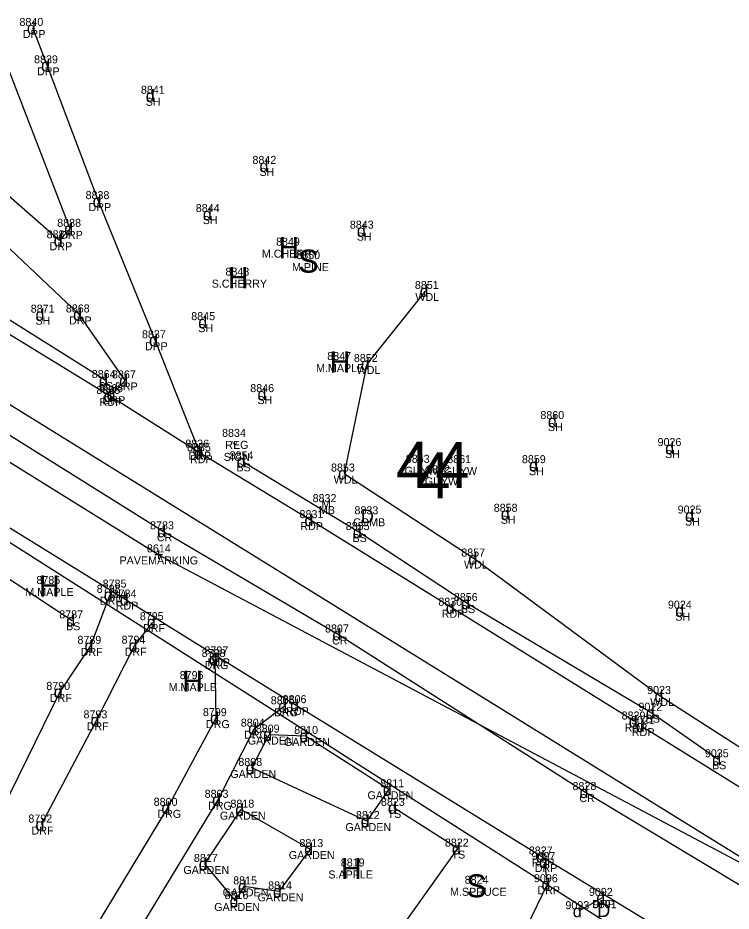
# Model space of a CAD drawing. Extents: x 69415 to 80913, y 7576 to 15059.
# Drawn here: x 77884.6 to 78062.8, y 12956.1 to 13179.4 of the extents above; entities that cross this region are included whole.
import ezdxf

# ---------------------------------------------------------------- set-up
doc = ezdxf.new("R2010")
doc.units = 0
for name, color, linetype in [('Level 11', 7, 'Continuous'), ('Level 12', 7, 'Continuous'), ('Level 14', 7, 'Continuous'), ('Level 15', 7, 'Continuous'), ('Level 43', 7, 'Continuous'), ('Level 45', 7, 'Continuous'), ('Level 46', 7, 'Continuous'), ('Level 47', 7, 'Continuous'), ('Level 48', 7, 'Continuous')]:
    doc.layers.add(name, color=color, linetype=linetype)

msp = doc.modelspace()

# ---------------------------------------------------------------- linework, layer by layer
at = {"layer": 'Level 11'}
for p, q in [((77897.68, 13126.63), (77877.49, 13178.8)), ((77891.9, 13167.5), (77888.34, 13176.83)), ((77904.77, 13133.56), (77891.9, 13167.5)), ((77870.35, 13145.35), (77895.03, 13123.77)), ((77899.89, 13105.23), (77866.57, 13136.78)), ((77918.86, 13098.79), (77904.77, 13133.56)), ((77895.03, 13123.77), (77897.68, 13126.63)), ((77907.51, 13084.89), (77855.14, 13117.01)), ((77911.41, 13088.74), (77899.89, 13105.23)), ((77929.73, 13071.45), (77918.86, 13098.79)), ((77908.27, 13085.31), (77911.41, 13088.74)), ((77930.11, 13070.56), (77907.51, 13084.89)), ((77957.66, 13053.83), (77930.11, 13070.56)), ((77871.92, 13058.45), (77911.53, 13033.98)), ((77992.99, 13031.93), (77957.66, 13053.83)), ((77907.55, 13035.17), (77902.75, 13022.41)), ((77911.53, 13033.98), (77934.46, 13019.78)), ((78038.7, 13003.51), (77992.99, 13031.93)), ((77913.75, 13022.44), (77918.32, 13028.34)), ((77902.75, 13022.41), (77895.05, 13010.92)), ((77904.25, 13003.8), (77913.75, 13022.44)), ((77933.78, 13019.11), (77934.09, 13004.36)), ((77934.46, 13019.78), (77954.13, 13007.59)), ((77895.05, 13010.92), (77880.63, 12981.5)), ((77943.63, 13001.72), (77951.11, 13007.31)), ((77954.13, 13007.59), (78015.5, 12969.77)), ((77890.47, 12977.76), (77904.25, 13003.8)), ((77934.09, 13004.36), (77921.94, 12981.94)), ((77934.6, 12983.95), (77943.63, 13001.72)), ((78040.51, 13002.35), (78086.37, 12973.81)), ((77912.5, 12947.44), (77934.6, 12983.95)), ((77921.94, 12981.94), (77904.19, 12952.44)), ((78015.5, 12969.77), (78057.41, 12944.28)), ((78016.92, 12962.84), (78016.25, 12968.4)), ((78011.78, 12952.23), (78016.92, 12962.84)), ((78030.6, 12959.43), (78024.73, 12956.11))]:
    msp.add_line(p, q, dxfattribs=at)
at = {"layer": 'Level 12'}
for p, q in [((77943.01, 12991.91), (77947.37, 13000.24)), ((77947.37, 13000.24), (77956.41, 12999.9)), ((77956.41, 12999.9), (77977.27, 12986.58)), ((77971.74, 12978.62), (77943.01, 12991.91)), ((77977.27, 12986.58), (77971.74, 12978.62)), ((77931.27, 12967.91), (77940.39, 12981.48)), ((77940.39, 12981.48), (77957.62, 12971.64)), ((77957.62, 12971.64), (77949.81, 12961.07)), ((77938.98, 12958.66), (77931.27, 12967.91)), ((77941.08, 12962.3), (77938.98, 12958.66)), ((77949.81, 12961.07), (77941.08, 12962.3))]:
    msp.add_line(p, q, dxfattribs=at)
at = {"layer": 'Level 14'}
for p, q in [((77986.47, 13111.1), (77971.79, 13092.85)), ((77971.79, 13092.85), (77966.08, 13065.48)), ((77966.08, 13065.48), (77998.63, 13044.24)), ((77998.63, 13044.24), (78045.15, 13009.88)), ((78045.15, 13009.88), (78073.47, 12991.56))]:
    msp.add_line(p, q, dxfattribs=at)
at = {"layer": 'Level 15'}
msp.add_line((77872.12, 13054.89), (78265.18, 12804.76), dxfattribs=at)
at = {"layer": 'Level 45'}
for p, q in [((77735.64, 13173.7), (78075.52, 12963.26)), ((77919.58, 13045.27), (77729.52, 13163.12)), ((78078.46, 12961.08), (77919.58, 13045.27))]:
    msp.add_line(p, q, dxfattribs=at)
at = {"layer": 'Level 48'}
for p, q in [((77906.36, 13088.84), (77856.67, 13120.07)), ((77881.52, 13075.74), (77920.88, 13051.04)), ((77940.76, 13068.52), (77969.77, 13050.87)), ((77862.42, 13052.33), (77898.19, 13028.79)), ((77920.88, 13051.04), (77964.67, 13025.26)), ((77969.77, 13050.87), (77996.83, 13033.11)), ((77996.83, 13033.11), (78042.97, 13005.71)), ((77964.67, 13025.26), (78026.42, 12985.87)), ((78042.97, 13005.71), (78059.56, 12994.07)), ((78026.42, 12985.87), (78074.53, 12956.86)), ((77994.53, 12971.75), (77978.56, 12981.92)), ((77975.6, 12945.31), (77994.53, 12971.75))]:
    msp.add_line(p, q, dxfattribs=at)

# ---------------------------------------------------------------- texts
at = {"layer": 'Level 12'}
msp.add_text('M', height=2.2, dxfattribs=at).set_placement((77960.39, 13056.73))
at = {"layer": 'Level 14'}
for s, height, p in [('H', 5.3, (77949.72, 13119.28)), ('S', 5.75, (77954.61, 13115.69)), ('H', 5.3, (77937.06, 13111.79)), ('H', 5.3, (77962.5, 13090.69)), ('H', 5.3, (77889.88, 13034.73)), ('H', 5.3, (77925.68, 13010.95)), ('H', 5.3, (77965.32, 12964.13)), ('S', 5.75, (77996.6, 12959.58))]:
    msp.add_text(s, height=height, dxfattribs=at).set_placement(p)
at = {"layer": 'Level 15'}
for s, height, p in [('4', 11.5, (77979.06, 13061.91)), ('4', 11.5, (77988.86, 13061.84)), ('4', 11.5, (77984.14, 13059.28)), ('D', 3.4, (77970.25, 13053.1)), ('I', 1.7, (77908.18, 13035.63)), ('D', 3.4, (78029.32, 12954.66))]:
    msp.add_text(s, height=height, dxfattribs=at).set_placement(p)
at = {"layer": 'Level 43'}
msp.add_text('Y', height=1.7, dxfattribs=at).set_placement((77938.02, 13071.79))
at = {"layer": 'Level 46'}
for s, p in [('8840', (77884.99, 13177.33)), ('DRP', (77885.83, 13174.33)), ('8839', (77888.64, 13168)), ('DRP', (77889.39, 13165)), ('8841', (77915.33, 13160.38)), ('SH', (77916.52, 13157.38)), ('8842', (77943.2, 13142.86)), ('SH', (77944.95, 13139.86)), ('8838', (77901.51, 13134.06)), ('DRP', (77902.26, 13131.06)), ('8844', (77929.04, 13130.82)), ('8888', (77894.42, 13127.13)), ('SH', (77930.79, 13127.82)), ('8843', (77967.53, 13126.68)), ('8887', (77891.77, 13124.27)), ('DRP', (77895.17, 13124.13)), ('8849', (77949.1, 13122.43)), ('SH', (77969.27, 13123.68)), ('DRP', (77892.52, 13121.27)), ('M.CHERRY', (77945.55, 13119.43)), ('8850', (77954.14, 13119.06)), ('M.PINE', (77953.09, 13116.06)), ('8848', (77936.45, 13114.94)), ('S.CHERRY', (77933.02, 13111.94)), ('8851', (77983.78, 13111.6)), ('WDL', (77983.89, 13108.6)), ('8871', (77887.8, 13105.68)), ('8868', (77896.58, 13105.73)), ('SH', (77888.99, 13102.68)), ('DRP', (77897.38, 13102.73)), ('8845', (77927.91, 13103.81)), ('SH', (77929.66, 13100.81)), ('8837', (77915.6, 13099.29)), ('DRP', (77916.35, 13096.29)), ('8847', (77961.89, 13093.84)), ('8852', (77968.53, 13093.35)), ('M.MAPLE', (77959.09, 13090.84)), ('8864', (77903.05, 13089.34)), ('8867', (77908.1, 13089.24)), ('WDL', (77969.21, 13090.35)), ('BS', (77904.8, 13086.34)), ('DRP', (77908.89, 13086.24)), ('8865', (77904.21, 13085.39)), ('8866', (77904.91, 13085.81)), ('8846', (77942.65, 13085.83)), ('RDP', (77905, 13082.39)), ('DRP', (77905.76, 13082.81)), ('SH', (77944.45, 13082.83)), ('8860', (78015.13, 13079.09)), ('SH', (78017.01, 13076.09)), ('8834', (77935.61, 13074.64)), ('8836', (77926.42, 13071.95)), ('8835', (77926.85, 13071.06)), ('REG', (77936.4, 13071.64)), ('9026', (78044.41, 13072.35)), ('DRP', (77927.22, 13068.95)), ('SIGN', (77936.02, 13068.64)), ('8854', (77937.5, 13069.02)), ('SH', (78046.3, 13069.35)), ('RDP', (77927.6, 13068.06)), ('8863', (77981.51, 13068.16)), ('8861', (77991.87, 13068.09)), ('8859', (78010.52, 13068.07)), ('BS', (77939.2, 13066.02)), ('8853', (77962.82, 13065.98)), ('GUYW', (77981.21, 13065.16)), ('8862', (77986.58, 13065.53)), ('GUYW', (77991, 13065.09)), ('SH', (78012.28, 13065.07)), ('WDL', (77963.49, 13062.98)), ('GUYW', (77986.28, 13062.53)), ('8832', (77958.23, 13058.33)), ('MB', (77959.8, 13055.33)), ('8833', (77968.69, 13055.3)), ('8858', (78003.48, 13055.92)), ('9025', (78049.43, 13055.48)), ('8831', (77954.97, 13054.33)), ('SH', (78005.23, 13052.92)), ('8783', (77917.62, 13051.54)), ('RDP', (77955.15, 13051.33)), ('8855', (77966.51, 13051.37)), ('COMB', (77968.34, 13052.3)), ('SH', (78051.26, 13052.48)), ('CR', (77919.32, 13048.54)), ('BS', (77968.21, 13048.37)), ('8614', (77916.84, 13045.77)), ('8857', (77995.37, 13044.74)), ('PAVEMARKING', (77909.99, 13042.77)), ('WDL', (77996.04, 13041.74)), ('8786', (77889.22, 13037.88)), ('M.MAPLE', (77886.47, 13034.88)), ('8788', (77904.29, 13035.67)), ('8785', (77905.77, 13036.98)), ('DRF', (77905.09, 13032.67)), ('MH', (77907.4, 13033.98)), ('8784', (77908.27, 13034.48)), ('8856', (77993.51, 13033.61)), ('RDP', (77909.02, 13031.48)), ('8830', (77989.64, 13032.43)), ('BS', (77995.27, 13030.61)), ('9024', (78047, 13031.72)), ('8787', (77894.93, 13029.29)), ('8795', (77915.06, 13028.84)), ('RDP', (77990.47, 13029.43)), ('SH', (78048.83, 13028.72)), ('BS', (77896.63, 13026.29)), ('DRF', (77915.85, 13025.84)), ('8807', (77961.33, 13025.76)), ('8789', (77899.48, 13022.91)), ('8794', (77910.49, 13022.94)), ('CR', (77963.1, 13022.76)), ('DRF', (77900.28, 13019.91)), ('DRF', (77911.28, 13019.94)), ('8798', (77930.52, 13019.61)), ('8797', (77931.2, 13020.28)), ('RDP', (77931.95, 13017.28)), ('DRG', (77931.27, 13016.61)), ('8796', (77925.02, 13014.1)), ('8790', (77891.7, 13011.42)), ('M.MAPLE', (77922.27, 13011.1)), ('9023', (78041.81, 13010.38)), ('DRF', (77892.58, 13008.42)), ('8806', (77950.74, 13008.09)), ('8805', (77947.77, 13007.81)), ('9022', (78039.63, 13006.21)), ('WDL', (78042.57, 13007.38)), ('8793', (77900.99, 13004.3)), ('8799', (77930.82, 13004.86)), ('DRG', (77948.6, 13004.81)), ('RDP', (77951.62, 13005.09)), ('8829', (78035.43, 13004.01)), ('DRG', (77931.58, 13001.86)), ('8804', (77940.29, 13002.22)), ('9021', (78037.74, 13002.85)), ('BS', (78041.41, 13003.21)), ('DRF', (77901.78, 13001.3)), ('DRG', (77941.11, 12999.22)), ('8809', (77944.02, 13000.74)), ('8810', (77953.63, 13000.4)), ('RDP', (78036.19, 13001.01)), ('RDP', (78037.99, 12999.85)), ('GARDEN', (77942.04, 12997.74)), ('GARDEN', (77951.08, 12997.4)), ('8808', (77939.67, 12992.41)), ('9035', (78056.23, 12994.57)), ('BS', (78058.01, 12991.57)), ('GARDEN', (77937.68, 12989.41)), ('8811', (77975.14, 12987.08)), ('8828', (78023.16, 12986.37)), ('8803', (77931.26, 12984.45)), ('GARDEN', (77971.94, 12984.08)), ('8800', (77918.52, 12982.44)), ('DRG', (77932.09, 12981.45)), ('8818', (77937.7, 12981.98)), ('8823', (77975.3, 12982.42)), ('CR', (78024.85, 12983.37)), ('DRG', (77919.43, 12979.44)), ('8812', (77969.05, 12979.12)), ('TS', (77976.97, 12979.42)), ('8792', (77887.21, 12978.26)), ('GARDEN', (77935.06, 12978.98)), ('DRF', (77888, 12975.26)), ('GARDEN', (77966.41, 12976.12)), ('8813', (77954.93, 12972.14)), ('8822', (77991.27, 12972.25)), ('8827', (78012.24, 12970.27)), ('8817', (77928.57, 12968.41)), ('GARDEN', (77952.29, 12969.14)), ('TS', (77992.94, 12969.25)), ('9097', (78012.92, 12968.9)), ('8819', (77965.27, 12967.28)), ('RDP', (78012.99, 12967.27)), ('DRP', (78013.74, 12965.9)), ('GARDEN', (77925.94, 12965.41)), ('S.APPLE', (77962.16, 12964.28)), ('8815', (77938.39, 12962.8)), ('8814', (77947.12, 12961.57)), ('8824', (77996.22, 12962.96)), ('9096', (78013.53, 12963.34)), ('GARDEN', (77935.75, 12959.8)), ('8816', (77936.23, 12959.16)), ('M.SPRUCE', (77992.56, 12959.96)), ('DRP', (78014.41, 12960.34)), ('9092', (78027.26, 12959.93)), ('GARDEN', (77944.48, 12958.57)), ('DRP', (78028.09, 12956.93)), ('9091', (78028.24, 12956.86)), ('GARDEN', (77933.65, 12956.16)), ('9093', (78021.39, 12956.61))]:
    msp.add_text(s, height=2, dxfattribs=at).set_placement(p)
at = {"layer": 'Level 47'}
for s, p in [('d', (77886.84, 13175.33)), ('d', (77890.4, 13166)), ('d', (77916.53, 13158.38)), ('d', (77944.96, 13140.86)), ('d', (77903.27, 13132.06)), ('d', (77930.8, 13128.82)), ('d', (77896.18, 13125.13)), ('d', (77969.28, 13124.68)), ('d', (77893.53, 13122.27)), ('d', (77984.97, 13109.6)), ('d', (77889, 13103.68)), ('d', (77898.39, 13103.73)), ('d', (77929.67, 13101.81)), ('d', (77917.36, 13097.29)), ('d', (77970.29, 13091.35)), ('d', (77904.86, 13087.34)), ('d', (77909.91, 13087.24)), ('d', (77906.01, 13083.39)), ('d', (77906.77, 13083.81)), ('d', (77944.46, 13083.83)), ('d', (78017.03, 13077.09)), ('d', (77928.23, 13069.95)), ('d', (78046.31, 13070.35)), ('d', (77928.61, 13069.06)), ('d', (77939.26, 13067.02)), ('d', (78012.29, 13066.07)), ('d', (77964.58, 13063.98)), ('d', (78005.24, 13053.92)), ('d', (77956.16, 13052.33)), ('d', (78051.27, 13053.48)), ('d', (77919.38, 13049.54)), ('d', (77968.27, 13049.37)), ('+', (77918.6, 13043.77)), ('d', (77997.13, 13042.74)), ('d', (77906.05, 13033.67)), ('d', (77910.03, 13032.48)), ('d', (77995.33, 13031.61)), ('d', (77991.49, 13030.43)), ('d', (78048.84, 13029.72)), ('d', (77896.69, 13027.29)), ('d', (77916.82, 13026.84)), ('d', (77963.17, 13023.76)), ('d', (77901.25, 13020.91)), ('d', (77912.25, 13020.94)), ('d', (77932.96, 13018.28)), ('d', (77932.28, 13017.61)), ('d', (77893.55, 13009.42)), ('d', (78043.65, 13008.38)), ('d', (77949.61, 13005.81)), ('d', (77952.63, 13006.09)), ('d', (77932.59, 13002.86)), ('d', (78041.47, 13004.21)), ('d', (77902.75, 13002.3)), ('d', (77942.13, 13000.22)), ('d', (78037.2, 13002.01)), ('d', (78039.01, 13000.85)), ('d', (77945.87, 12998.74)), ('d', (77954.91, 12998.4)), ('d', (78058.06, 12992.57)), ('d', (77941.51, 12990.41)), ('d', (77975.77, 12985.08)), ('d', (77933.1, 12982.45)), ('d', (78024.92, 12984.37)), ('d', (77920.44, 12980.44)), ('d', (77977.06, 12980.42)), ('d', (77938.89, 12979.98)), ('d', (77888.97, 12976.26)), ('d', (77970.24, 12977.12)), ('d', (77956.12, 12970.14)), ('d', (77993.03, 12970.25)), ('d', (78014, 12968.27)), ('d', (78014.75, 12966.9)), ('d', (77929.77, 12966.41)), ('d', (77939.58, 12960.8)), ('d', (78015.42, 12961.34)), ('d', (77948.31, 12959.57)), ('d', (78029.1, 12957.93)), ('d', (77937.48, 12957.16)), ('d', (78023.23, 12954.61))]:
    msp.add_text(s, height=3, dxfattribs=at).set_placement(p)

doc.saveas('drawing.dxf')
